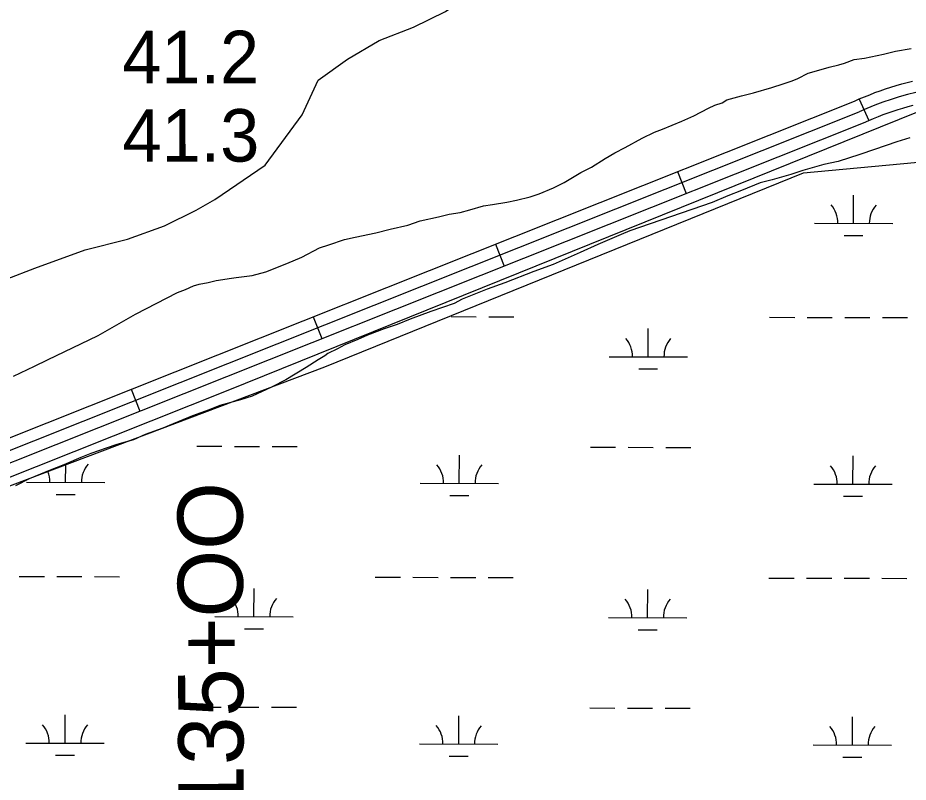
# Model space of a CAD drawing. Extents: x 3180038 to 3217926, y 922069 to 947485.
# Drawn here: x 3187547 to 3188682, y 930412 to 931387 of the extents above; entities that cross this region are included whole.
import ezdxf

# ---------------------------------------------------------------- set-up
doc = ezdxf.new("R2010")
doc.units = 0
for name, color, linetype in [('V-RIVR-RANG', 7, 'Continuous'), ('V-RIVR-RANG-IDEN', 7, 'Continuous'), ('V-ROAD-CNTR', 7, 'Continuous'), ('V-SITE-VEGE', 7, 'Continuous'), ('V-TOPO-SHOR', 7, 'Continuous'), ('V-WETL-SWMP', 7, 'Continuous')]:
    doc.layers.add(name, color=color, linetype=linetype)

msp = doc.modelspace()

# ---------------------------------------------------------------- linework, layer by layer
at = {"layer": 'V-ROAD-CNTR'}
for p, q in [((3188619.4, 931283.4), (3188631.7, 931256)), ((3188387.8, 931190.8), (3188399, 931162.9)), ((3188155.6, 931098.2), (3188166.7, 931070.3)), ((3187923.4, 931005.6), (3187934.5, 930977.8)), ((3187691.2, 930913.1), (3187702.3, 930885.2))]:
    msp.add_line(p, q, dxfattribs=at)
for points in [[(3186962.3, 930659.2), (3186999.6, 930661.9), (3187019.2, 930663.2), (3187037.9, 930666.2), (3187070.5, 930674.6), (3187103.2, 930684.2), (3187140.1, 930695.8), (3187176.6, 930708.2), (3187245.5, 930734.2), (3187313.8, 930762.6), (3188613.4, 931280.7), (3188619.6, 931283.5), (3188626.3, 931286.3), (3188632.9, 931288.9), (3188639.6, 931291.5), (3188646.4, 931294), (3188653.1, 931296.3), (3188659.9, 931298.6), (3188666.8, 931300.7), (3188673.7, 931302.6), (3188680.7, 931304.5), (3188687.6, 931306.2)], [(3186954.1, 930628.5), (3187001.7, 930632), (3187022.6, 930633.4), (3187044, 930636.8), (3187078.5, 930645.6), (3187111.9, 930655.5), (3187149.4, 930667.3), (3187186.7, 930679.9), (3187256.6, 930706.3), (3187325.2, 930734.9), (3188625.1, 931253.1), (3188631.6, 931256), (3188637.7, 931258.5), (3188643.9, 931261), (3188650.1, 931263.5), (3188656.3, 931265.7), (3188662.7, 931267.9), (3188669, 931270), (3188675.3, 931271.9), (3188681.7, 931273.7), (3188688.2, 931275.5)], [(3187319.5, 930748.8), (3188619.3, 931266.9)]]:
    msp.add_lwpolyline(points, dxfattribs=at)
msp.add_arc((3188783.9, 930906.1), 396.6, 89.2051, 114.5197, dxfattribs=at)
at = {"layer": 'V-SITE-VEGE'}
for p, q in [((3188650.3, 931340.8), (3188665.6, 931344.6)), ((3188665.6, 931344.6), (3188685.9, 931347.8)), ((3188600.9, 931329.3), (3188613.2, 931333.8)), ((3188613.2, 931333.8), (3188626.3, 931335.4)), ((3188626.3, 931335.4), (3188650.3, 931340.8)), ((3188554.4, 931316.3), (3188571.1, 931320.9)), ((3188571.1, 931320.9), (3188581.3, 931323.9)), ((3188581.3, 931323.9), (3188593.6, 931327)), ((3188593.6, 931327), (3188600.9, 931329.3)), ((3188534.1, 931306.6), (3188541.4, 931309.6)), ((3188541.4, 931309.6), (3188554.4, 931316.3)), ((3188484.8, 931291.4), (3188508, 931298.2)), ((3188508, 931298.2), (3188522.5, 931302.8)), ((3188522.5, 931302.8), (3188534.1, 931306.6)), ((3188450.6, 931282.2), (3188469.5, 931287.5)), ((3188469.5, 931287.5), (3188484.8, 931291.4)), ((3188427.4, 931271.7), (3188435.4, 931275.5)), ((3188435.4, 931275.5), (3188444.9, 931278.5)), ((3188444.9, 931278.5), (3188450.6, 931282.2)), ((3188408.6, 931262), (3188427.4, 931271.7)), ((3188368.8, 931244.8), (3188393.4, 931255.3)), ((3188393.4, 931255.3), (3188408.6, 931262)), ((3188342.7, 931233.5), (3188358.6, 931241)), ((3188358.6, 931241), (3188368.8, 931244.8)), ((3188320.9, 931221.6), (3188342.7, 931233.5)), ((3188684.1, 931234), (3188667.4, 931228.7)), ((3188307.9, 931214.8), (3188320.9, 931221.6)), ((3188639.1, 931218.9), (3188620.2, 931212.8)), ((3188667.4, 931228.7), (3188639.1, 931218.9)), ((3188278.3, 931196.3), (3188295.6, 931207.4)), ((3188295.6, 931207.4), (3188307.9, 931214.8)), ((3188620.2, 931212.8), (3188592.6, 931203.7)), ((3188264.5, 931189.5), (3188278.3, 931196.3)), ((3188574.4, 931199.9), (3188547.6, 931192.2)), ((3188592.6, 931203.7), (3188574.4, 931199.9)), ((3188243.5, 931176.9), (3188264.5, 931189.5)), ((3188532.3, 931187), (3188508.4, 931180.1)), ((3188547.6, 931192.2), (3188532.3, 931187)), ((3188229.8, 931170.1), (3188243.5, 931176.9)), ((3188493.1, 931176.3), (3188469.2, 931166.5)), ((3188508.4, 931180.1), (3188493.1, 931176.3)), ((3188200, 931158.8), (3188211.6, 931162.6)), ((3188211.6, 931162.6), (3188229.8, 931170.1)), ((3188469.2, 931166.5), (3188451.8, 931159.7)), ((3188152, 931148.8), (3188170.2, 931151.9)), ((3188170.2, 931151.9), (3188182.6, 931154.3)), ((3188182.6, 931154.3), (3188200, 931158.8)), ((3188432.2, 931151.5), (3188327, 931115.2)), ((3188451.8, 931159.7), (3188432.2, 931151.5)), ((3188096.8, 931136.4), (3188110.6, 931138.8)), ((3188110.6, 931138.8), (3188123, 931141.9)), ((3188123, 931141.9), (3188140.4, 931147.2)), ((3188140.4, 931147.2), (3188152, 931148.8)), ((3188043.8, 931122.6), (3188059.8, 931128)), ((3188059.8, 931128), (3188083, 931133.3)), ((3188083, 931133.3), (3188096.8, 931136.4)), ((3188003.1, 931112.7), (3188021.3, 931117.3)), ((3188021.3, 931117.3), (3188043.8, 931122.6)), ((3187943.5, 931097.4), (3187963.1, 931104.2)), ((3187963.1, 931104.2), (3187976.9, 931107.2)), ((3187976.9, 931107.2), (3188003.1, 931112.7)), ((3188316.1, 931110.7), (3188286.4, 931097.9)), ((3188327, 931115.2), (3188316.1, 931110.7)), ((3187908.7, 931081.6), (3187931.2, 931093.6)), ((3187931.2, 931093.6), (3187943.5, 931097.4)), ((3188286.4, 931097.9), (3188263.9, 931087.4)), ((3187889.9, 931073.4), (3187908.7, 931081.6)), ((3188263.9, 931087.4), (3188229.1, 931072.4)), ((3187863.1, 931062.8), (3187889.9, 931073.4)), ((3188229.1, 931072.4), (3188204.5, 931063.4)), ((3187845.6, 931058.2), (3187863.1, 931062.8)), ((3188204.5, 931063.4), (3188167.5, 931049)), ((3187778, 931047.2), (3187789.6, 931049.5)), ((3187789.6, 931049.5), (3187799.8, 931051.8)), ((3187799.8, 931051.8), (3187819.4, 931055)), ((3187819.4, 931055), (3187825.3, 931055.8)), ((3187825.3, 931055.8), (3187845.6, 931058.2)), ((3188167.5, 931049), (3188145, 931040.8)), ((3187696.9, 931009), (3187750.4, 931036.6)), ((3187750.4, 931036.6), (3187760.6, 931040.4)), ((3187760.6, 931040.4), (3187770.7, 931044.9)), ((3187770.7, 931044.9), (3187778, 931047.2)), ((3188145, 931040.8), (3188113.1, 931028)), ((3188113.1, 931028), (3188103, 931022.7)), ((3188103, 931022.7), (3188073.2, 931012.2)), ((3187664.3, 930990.4), (3187696.9, 931009)), ((3188047.1, 931002.4), (3188030.4, 930995.6)), ((3188073.2, 931012.2), (3188047.1, 931002.4)), ((3188030.4, 930995.6), (3188013.7, 930990.3)), ((3187584.6, 930950.8), (3187649.1, 930981.5)), ((3187649.1, 930981.5), (3187664.3, 930990.4)), ((3187992.7, 930982), (3187980.4, 930976.8)), ((3188013.7, 930990.3), (3187992.7, 930982)), ((3187963.7, 930970), (3187954.3, 930964.8)), ((3187980.4, 930976.8), (3187963.7, 930970)), ((3187942, 930958.8), (3187938.4, 930955.8)), ((3187954.3, 930964.8), (3187942, 930958.8)), ((3187568, 930942.6), (3187584.6, 930950.8)), ((3187929.7, 930950.6), (3187914.5, 930941)), ((3187938.4, 930955.8), (3187929.7, 930950.6)), ((3187541.2, 930929.8), (3187568, 930942.6)), ((3187914.5, 930941), (3187888.5, 930925.3)), ((3187888.5, 930925.3), (3187870.4, 930915.6)), ((3187870.4, 930915.6), (3187845.7, 930904.4)), ((3187830.5, 930899.8), (3187804.3, 930892.2)), ((3187845.7, 930904.4), (3187830.5, 930899.8)), ((3187804.3, 930892.2), (3187790.6, 930886.9)), ((3187769.5, 930879.4), (3187744.9, 930868.9)), ((3187790.6, 930886.9), (3187769.5, 930879.4)), ((3187744.9, 930868.9), (3187731.8, 930863.6)), ((3187709.3, 930855.3), (3187694.1, 930848.6)), ((3187731.8, 930863.6), (3187709.3, 930855.3)), ((3187694.1, 930848.6), (3187673, 930842.5)), ((3187659.3, 930837.9), (3187639.7, 930831.1)), ((3187673, 930842.5), (3187659.3, 930837.9)), ((3187627.3, 930825.9), (3187605.6, 930816.9)), ((3187639.7, 930831.1), (3187627.3, 930825.9)), ((3187588.2, 930810.1), (3187561.4, 930798.8)), ((3187605.6, 930816.9), (3187588.2, 930810.1)), ((3187561.4, 930798.8), (3187544, 930789.9))]:
    msp.add_line(p, q, dxfattribs=at)
at = {"layer": 'V-TOPO-SHOR'}
for points in [[(3187497.3, 931040.5), (3187568.3, 931067.5), (3187632.5, 931091.1), (3187686.5, 931104.6), (3187733.8, 931121.5), (3187774.3, 931141.8), (3187798, 931155.3), (3187862.2, 931199.2), (3187909.5, 931263.4), (3187929.7, 931307.3), (3187966.9, 931334.3), (3188007.4, 931358), (3188051.3, 931374.9), (3188091.9, 931395.1), (3188112.1, 931408.7), (3188125.6, 931425.6), (3188143.4, 931453.7)], [(3186909.6, 930473), (3187078.5, 930594.6), (3187179.8, 930658.8), (3187814.9, 930912.1), (3188693.1, 931266.8), (3188753.9, 931293.8), (3188909.3, 931293.8), (3189125.5, 931276.9), (3189328.2, 931256.7), (3189416, 931256.7), (3189490.3, 931266.8), (3189571.4, 931290.4), (3189709.9, 931320.8), (3189750.4, 931327.6), (3189757.2, 931327.6), (3189743.7, 931287.1), (3189696.2, 931243.8)]]:
    msp.add_lwpolyline(points, dxfattribs=at)
at = {"layer": 'V-WETL-SWMP'}
for p, q in [((3188548.5, 931189.4), (3188840.4, 931216)), ((3187938.1, 930941.6), (3188548.5, 931189.4)), ((3188612.3, 931124.7), (3188612.4, 931160.7)), ((3188562.3, 931124.8), (3188662.3, 931124.6)), ((3188600.3, 931109.3), (3188624.3, 931109.2)), ((3188099.3, 931005.8), (3188131.3, 931005.7)), ((3188147.3, 931005.7), (3188179.3, 931005.6)), ((3188505.2, 931004.9), (3188537.2, 931004.8)), ((3188553.2, 931004.7), (3188585.2, 931004.7)), ((3188601.2, 931004.6), (3188633.2, 931004.6)), ((3188649.2, 931004.5), (3188681.2, 931004.5)), ((3188350.5, 930954.5), (3188350.5, 930990.5)), ((3188300.5, 930954.6), (3188400.5, 930954.3)), ((3187141.9, 930640.6), (3187938.1, 930941.6)), ((3188338.4, 930939.1), (3188362.4, 930939)), ((3187774.9, 930840.3), (3187806.9, 930840.3)), ((3187822.9, 930840.2), (3187854.9, 930840.1)), ((3187870.9, 930840.1), (3187902.9, 930840)), ((3188276.8, 930839.2), (3188308.8, 930839.1)), ((3188324.8, 930839.1), (3188356.8, 930839)), ((3188372.8, 930839), (3188404.8, 930838.9)), ((3188109.6, 930793.1), (3188109.7, 930829.1)), ((3188611.5, 930792), (3188611.6, 930828)), ((3187607.7, 930794.3), (3187607.8, 930816.7)), ((3187557.7, 930794.4), (3187657.7, 930794.2)), ((3188059.6, 930793.3), (3188159.6, 930793)), ((3188561.5, 930792.1), (3188661.5, 930791.9)), ((3187595.7, 930778.9), (3187619.7, 930778.8)), ((3188097.6, 930777.7), (3188121.6, 930777.7)), ((3188599.5, 930776.6), (3188623.5, 930776.6)), ((3187548.6, 930674.3), (3187580.6, 930674.3)), ((3187596.6, 930674.2), (3187628.6, 930674.2)), ((3187644.6, 930674.1), (3187676.6, 930674)), ((3188002.5, 930673.3), (3188034.5, 930673.2)), ((3188050.5, 930673.2), (3188082.5, 930673.1)), ((3188098.5, 930673.1), (3188130.5, 930673)), ((3188146.5, 930673), (3188178.5, 930672.9)), ((3188504.4, 930672.2), (3188536.4, 930672.1)), ((3188552.4, 930672.1), (3188584.4, 930672)), ((3188600.4, 930672), (3188632.4, 930671.9)), ((3188648.4, 930671.9), (3188680.4, 930671.8)), ((3187847.8, 930622.9), (3187847.9, 930658.9)), ((3188349.7, 930621.8), (3188349.8, 930657.8)), ((3187797.8, 930623), (3187897.8, 930622.8)), ((3188299.7, 930621.9), (3188399.7, 930621.7)), ((3187835.8, 930607.5), (3187859.8, 930607.5)), ((3188337.7, 930606.4), (3188361.7, 930606.3)), ((3187774.1, 930507.7), (3187806.1, 930507.6)), ((3187822.1, 930507.5), (3187854.1, 930507.5)), ((3187870.1, 930507.4), (3187902.1, 930507.4)), ((3188276, 930506.5), (3188308, 930506.4)), ((3188324, 930506.4), (3188356, 930506.3)), ((3188372, 930506.3), (3188404, 930506.2)), ((3187607, 930461.6), (3187607.1, 930497.6)), ((3188108.9, 930460.5), (3188109, 930496.5)), ((3188610.8, 930459.3), (3188610.9, 930495.3)), ((3187557, 930461.7), (3187657, 930461.5)), ((3188058.9, 930460.6), (3188158.9, 930460.4)), ((3188560.8, 930459.4), (3188660.8, 930459.2)), ((3187594.9, 930446.2), (3187618.9, 930446.1)), ((3188096.8, 930445.1), (3188120.8, 930445)), ((3188598.8, 930443.9), (3188622.8, 930443.9))]:
    msp.add_line(p, q, dxfattribs=at)
for centre, start, end in [((3188557, 931125.3), 359.099, 40.6427), ((3188667.5, 931125), 139.099, 180.6427), ((3188295.2, 930955.1), 359.099, 40.6427), ((3188405.7, 930954.8), 139.099, 180.6427), ((3187663, 930794.6), 139.099, 180.6427), ((3188054.4, 930793.7), 359.099, 40.6427), ((3188164.9, 930793.5), 139.099, 180.6427), ((3188556.3, 930792.6), 359.099, 40.6427), ((3188666.8, 930792.4), 139.099, 180.6427), ((3187552.5, 930794.9), 359.099, 22.1329), ((3187792.6, 930623.5), 359.099, 40.6427), ((3187903.1, 930623.3), 139.099, 180.6427), ((3188294.5, 930622.4), 359.099, 40.6427), ((3188405, 930622.1), 139.099, 180.6427), ((3187551.7, 930462.2), 359.099, 40.6427), ((3187662.2, 930461.9), 139.099, 180.6427), ((3188053.6, 930461.1), 359.099, 40.6427), ((3188164.1, 930460.8), 139.099, 180.6427), ((3188555.5, 930459.9), 359.099, 40.6427), ((3188666, 930459.7), 139.099, 180.6427)]:
    msp.add_arc(centre, 35.2, start, end, dxfattribs=at)

# ---------------------------------------------------------------- texts
at = {"layer": 'V-RIVR-RANG'}
for s, p in [('41.2', (3187680, 931303.4)), ('41.3', (3187680.3, 931203.4))]:
    msp.add_text(s, height=67, rotation=0.0483, dxfattribs=at).set_placement(p)
at = {"layer": 'V-RIVR-RANG-IDEN'}
msp.add_text('R-135+OO', height=83, rotation=90.1935, dxfattribs=at).set_placement((3187835.1, 930255))

doc.saveas('drawing.dxf')
